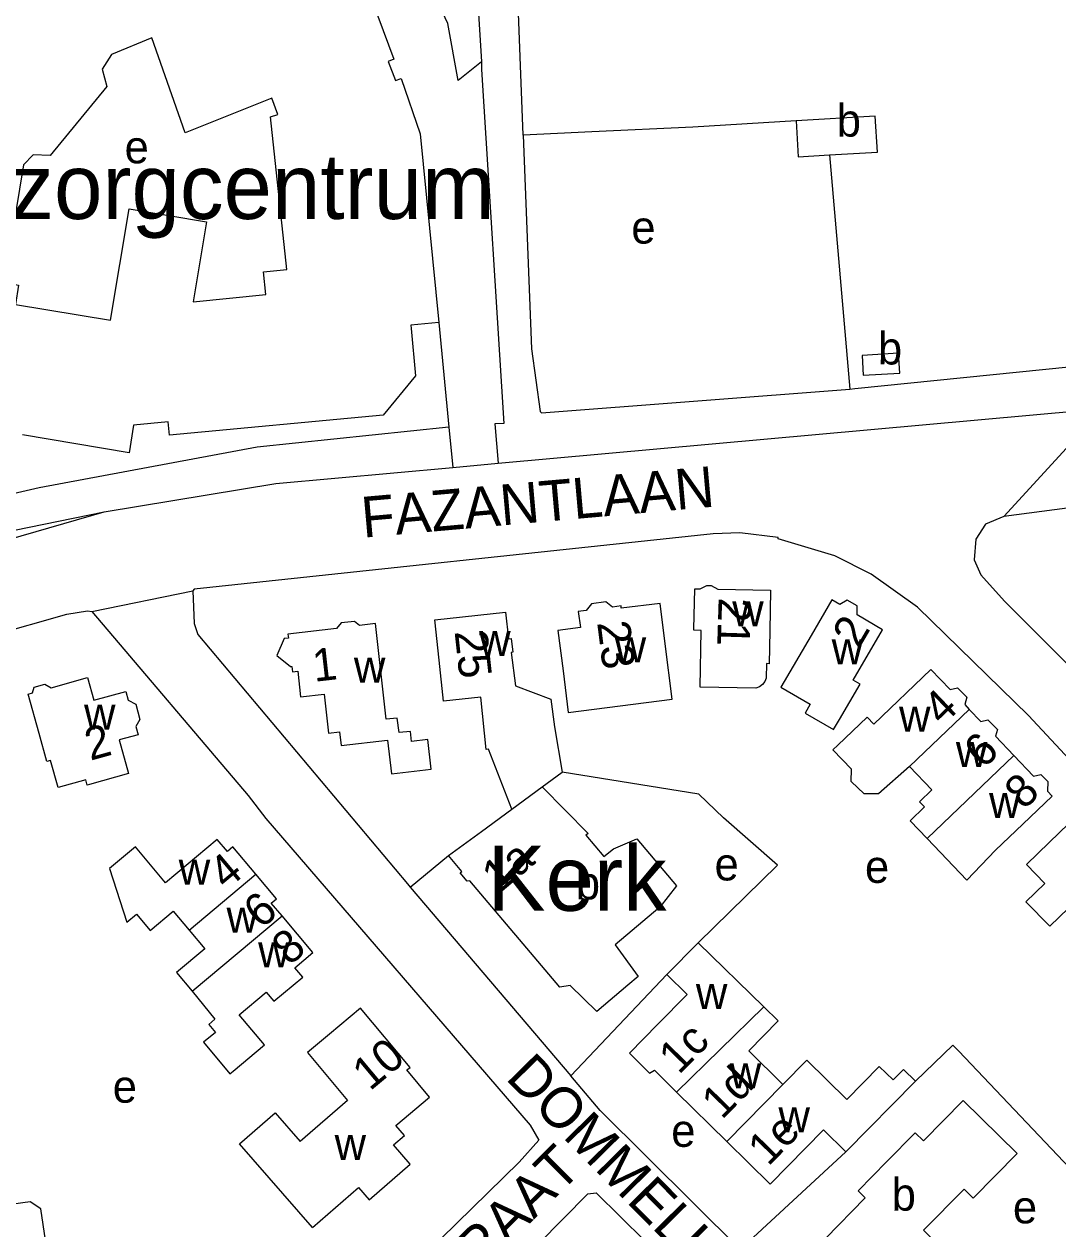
# Model space of a CAD drawing. Extents: x 161775 to 163181, y 382878 to 383925.
# Drawn here: x 162004.9 to 162131.9, y 383389.4 to 383537.4 of the extents above; entities that cross this region are included whole.
import ezdxf

# ---------------------------------------------------------------- set-up
doc = ezdxf.new("R2010")
doc.units = 0
for name, color, linetype in [('BLT_Basislijn', 7, 'Continuous'), ('BLT_Bebouwing', 7, 'Continuous'), ('BLT_Bebouwing_beschrifting', 7, 'Continuous'), ('BLT_Centroide', 7, 'Continuous'), ('BLT_Huisnummer', 7, 'Continuous'), ('BLT_Huisnummer_ tussenligend', 7, 'Continuous'), ('BLT_Onderverdeling_panden', 7, 'Continuous'), ('BLT_Straatnaam', 7, 'Continuous'), ('BLT_Vlakafsluiter', 7, 'Continuous')]:
    doc.layers.add(name, color=color, linetype=linetype)

msp = doc.modelspace()

# ---------------------------------------------------------------- linework, layer by layer
at = {"layer": 'BLT_Basislijn'}
for p, q in [((162074.67, 383524.13), (162066.25, 383523.72)), ((162103.84, 383521.3), (162106.37, 383492.55)), ((162055.89, 383500.73), (162057.11, 383487.85)), ((162063.18, 383483.44), (162137.41, 383490.17)), ((162057.11, 383487.85), (162057.58, 383482.93)), ((162062.77, 383488.27), (162063.18, 383483.44)), ((162052.36, 383431.37), (162057.06, 383435.26)), ((162087.71, 383424.55), (162097.48, 383434.06)), ((162052.36, 383431.37), (162072.1, 383408.19)), ((162092.87, 383386.85), (162105.88, 383398.85))]:
    msp.add_line(p, q, dxfattribs=at)
for points in [[(162066.25, 383523.72), (162064.33, 383574.02)], [(162061.11, 383532.76), (162061.1, 383531.81), (162063.88, 383488.3), (162062.77, 383488.27)], [(162099.75, 383525.49), (162087.08, 383524.73), (162074.67, 383524.13)], [(162066.25, 383523.72), (162067.24, 383497.51), (162068.34, 383489.79), (162068.5, 383489.63), (162106.37, 383492.55)], [(162057.11, 383487.85), (162033.55, 383485.42), (162006.78, 383480.4), (161990.83, 383476.74), (161984.63, 383476.87), (161983.29, 383477.14), (161978.85, 383478.81), (161976.83, 383480.24), (161973.93, 383483.29), (161972.63, 383485.26), (161970.99, 383488.68), (161970, 383493.53), (161968.55, 383506.6), (161967.45, 383522.13)], [(162106.37, 383492.55), (162106.96, 383492.6), (162150.23, 383497)], [(162211.14, 383490.01), (162196.65, 383487.24), (162159.15, 383481.38), (162125.25, 383476.9)], [(162014.8, 383477.46), (162035.87, 383480.96), (162057.58, 383482.93)], [(162057.58, 383482.93), (162063.18, 383483.44)], [(161974.85, 383465.82), (161980.14, 383467.21), (161991.24, 383470.67), (162014.8, 383477.46)], [(161988.9, 383472.18), (162014.8, 383477.46)], [(162125.25, 383476.9), (162123.02, 383475.95), (162121.82, 383474.13), (162121.64, 383471.58), (162122.43, 383469.75), (162125.33, 383466.48), (162163.61, 383428.2), (162170.77, 383419.99), (162181.31, 383409.13), (162201.49, 383387.36), (162220.16, 383368.12), (162237.6, 383349.53), (162241.27, 383346.24)], [(162234.37, 383341.1), (162200.53, 383376.54), (162198.79, 383378.55), (162180.32, 383397.96), (162171.16, 383407.28), (162152.54, 383427.04), (162145.46, 383434.09), (162144.51, 383435.3), (162141.14, 383438.66), (162128.28, 383452.45), (162114.65, 383465.76), (162108.97, 383469.83), (162104.5, 383472.05), (162097.57, 383474.16), (162097.57, 383474.32), (162092.85, 383474.91), (162089.56, 383474.77), (162025.83, 383467.96), (162025.67, 383467.75)], [(162025.67, 383467.75), (162025.82, 383463.74), (162026.27, 383462.41), (162052.03, 383431.77), (162052.36, 383431.37)], [(161973.32, 383454.41), (162010.19, 383464.89), (162012.73, 383465.31), (162013.27, 383465.24)], [(162013.27, 383465.24), (162032.46, 383442.64), (162034.65, 383439.79), (162067.09, 383402.14), (162068.18, 383400.29), (162065.73, 383397.61), (162046.55, 383378.8)], [(162097.48, 383434.06), (162090.82, 383439.89), (162087.79, 383442.81), (162071.02, 383445.48)], [(162072.1, 383408.19), (162083.86, 383420.63)], [(162114.43, 383407.55), (162118.99, 383411.97), (162119.75, 383411.23), (162136.39, 383393.66), (162138.37, 383391.5), (162138.68, 383390.7), (162113.58, 383365.34)], [(162092.87, 383386.85), (162075.69, 383403.95), (162072.1, 383408.19)], [(162036.52, 383357.08), (162059.8, 383379.79), (162066.65, 383386.36), (162068.12, 383387.55), (162074.17, 383393.72), (162075.21, 383393.82), (162093.13, 383376.16), (162097.9, 383371.1)]]:
    msp.add_lwpolyline(points, dxfattribs=at)
at = {"layer": 'BLT_Bebouwing'}
for p, q in [((162059.98, 383551.43), (162061.11, 383532.76)), ((162068.57, 383443.68), (162071.02, 383445.48)), ((162083.86, 383420.63), (162087.71, 383424.55)), ((162095.78, 383416.69), (162087.71, 383424.55)), ((162105.88, 383398.85), (162114.43, 383407.55)), ((162085.08, 383406.2), (162091.26, 383400.12))]:
    msp.add_line(p, q, dxfattribs=at)
for points in [[(162061.11, 383532.76), (162058.27, 383530.46), (162056.98, 383537.43), (162053.91, 383543.98), (162053.43, 383550.99)], [(162044.21, 383549.62), (162050.36, 383533.06), (162049.67, 383532.8), (162050.57, 383530.45), (162051.25, 383530.69), (162053.6, 383523.88), (162055.89, 383500.73)], [(162103.84, 383521.3), (162109.74, 383521.65), (162109.47, 383526.08), (162099.75, 383525.49)], [(162099.75, 383525.49), (162100.01, 383521.07), (162103.84, 383521.3)], [(162055.89, 383500.73), (162052.44, 383500.41), (162052.48, 383500), (162053.02, 383494.18), (162049.04, 383489.36), (162022.81, 383486.88), (162022.65, 383488.52), (162018.37, 383488.12), (162017.85, 383484.72), (162004.75, 383486.93)], [(162107.86, 383496.67), (162108.01, 383494.24), (162112.51, 383494.51), (162112.35, 383496.94), (162107.86, 383496.67)], [(162096.51, 383462.84), (162096.44, 383458.82), (162096.12, 383458.83), (162096.09, 383457.04), (162095.93, 383456.64), (162095.63, 383456.25), (162095.25, 383455.98), (162094.82, 383455.82), (162087.97, 383455.94), (162088.1, 383462.9), (162087.21, 383462.92), (162087.21, 383463.04), (162087.3, 383468.01), (162087.99, 383468), (162088.78, 383468.44), (162089.34, 383468.43), (162090.14, 383467.96), (162096.6, 383467.84), (162096.51, 383462.84)], [(162105.1, 383451.98), (162107.61, 383456.3), (162106.76, 383456.79), (162110.38, 383462.99), (162107.24, 383464.82), (162107.25, 383465.92), (162106.03, 383466.63), (162105.11, 383466.1), (162104.14, 383466.66), (162101.6, 383462.3), (162097.89, 383455.93), (162101.5, 383453.83), (162100.87, 383452.76), (162104.36, 383450.72), (162105.1, 383451.98)], [(162064.84, 383440.94), (162061.97, 383448.33), (162061.71, 383448.3), (162061.02, 383454.72), (162056.46, 383454.23), (162055.91, 383459.27), (162055.37, 383464.21), (162064.08, 383465.16), (162064.43, 383461.89), (162064.77, 383461.93), (162064.96, 383460.22)], [(162083.67, 383461.26), (162083.05, 383466.22), (162078.29, 383465.62), (162078.26, 383465.91), (162077.2, 383465.78), (162076.39, 383466.4), (162074.62, 383466.18), (162073.97, 383465.35), (162073.01, 383465.23), (162073.26, 383463.25), (162070.51, 383462.91), (162071.13, 383457.93), (162071.77, 383452.82), (162084.52, 383454.46), (162083.67, 383461.26)], [(162048.11, 383463.74), (162046.12, 383463.52), (162045.51, 383464.01), (162043.87, 383463.83), (162043.32, 383463.14), (162037.34, 383462.46), (162037.4, 383461.96), (162036.89, 383461.9), (162035.99, 383459.83), (162037.68, 383458.47), (162037.84, 383458.49), (162037.92, 383457.83), (162038.55, 383457.9), (162038.9, 383454.76), (162041.81, 383455.09), (162042.35, 383450.3), (162043.7, 383450.46), (162043.89, 383448.79), (162049.59, 383449.44), (162050.05, 383445.31), (162054.93, 383445.86), (162054.52, 383449.49), (162052.53, 383449.27), (162052.39, 383450.51), (162050.99, 383450.36), (162050.78, 383452.14), (162049.43, 383451.99), (162048.11, 383463.74)], [(162064.96, 383460.22), (162064.75, 383460.2), (162065.3, 383456.1), (162069.65, 383454.45), (162070.1, 383451.06), (162071.02, 383445.48)], [(162113.68, 383446.18), (162109.87, 383442.85), (162108.13, 383442.85), (162106.52, 383444.34), (162106.54, 383445.87), (162104.27, 383448.23), (162104.88, 383448.81), (162108.49, 383452.26), (162109.3, 383451.41), (162116.3, 383458.11), (162118.66, 383455.64), (162119.59, 383455.87), (162120.72, 383454.69), (162120.46, 383453.79), (162121.02, 383453.2)], [(162012.96, 383443.98), (162012.69, 383443.9), (162012.51, 383444.54), (162009.13, 383443.6), (162008.21, 383446.93), (162007.74, 383446.8), (162006.78, 383450.26), (162005.44, 383455.07), (162005.99, 383455.22), (162006.17, 383455.94), (162007.5, 383456.31), (162008.27, 383455.87), (162012.72, 383457.11), (162013.5, 383454.32), (162017.43, 383455.41), (162017.73, 383454.36), (162018.65, 383453.83), (162019.17, 383451.98), (162018.67, 383451.1), (162018.95, 383450.1), (162016.63, 383449.45), (162017.77, 383445.32), (162012.96, 383443.98)], [(162121.02, 383453.2), (162122.43, 383451.73), (162123.31, 383451.94), (162124.47, 383450.73), (162124.23, 383449.9), (162126.49, 383447.54)], [(162126.49, 383447.54), (162128.9, 383445.02), (162129.79, 383445.23), (162130.65, 383444.33), (162130.62, 383443.17), (162131.2, 383442.56), (162127.59, 383439.11), (162124.25, 383435.91), (162120.73, 383432.23), (162115.83, 383437.35)], [(162115.83, 383437.35), (162113.75, 383439.52), (162115.53, 383441.22), (162114.92, 383441.86), (162116.43, 383443.31), (162113.68, 383446.18)], [(162068.57, 383443.68), (162074.21, 383437.97), (162073.94, 383437.74), (162076.15, 383435.12), (162077.32, 383436.1), (162080.2, 383437.29), (162085.05, 383431.55), (162083.04, 383428.92), (162077.55, 383424.27), (162080.35, 383420.4), (162079.09, 383419.33), (162075.27, 383416.1), (162072.01, 383419.31), (162070.76, 383419.08), (162059.68, 383432.17), (162059.37, 383432.11), (162058.51, 383433.14), (162058.71, 383433.31), (162057.06, 383435.26)], [(162057.06, 383435.26), (162061.1, 383438.2), (162064.84, 383440.94)], [(162133.2, 383428.81), (162130.9, 383426.57), (162127.97, 383429.59), (162130.28, 383431.83), (162128.04, 383434.14), (162130.84, 383436.86), (162134.43, 383440.34), (162139.6, 383435.01)], [(162033.4, 383432.98), (162030.6, 383436.32), (162029.91, 383435.74), (162028.66, 383437.23), (162022.32, 383431.92), (162018.61, 383436.34), (162015.42, 383433.66), (162017.57, 383427.06), (162018.76, 383428.06), (162020.44, 383426.05), (162023.26, 383428.42), (162025.2, 383426.11)], [(162036.62, 383427.84), (162035.31, 383429.4), (162035.95, 383429.94), (162033.4, 383432.98)], [(162025.57, 383418.58), (162028.37, 383415.14), (162027.63, 383414.52), (162028.45, 383413.54), (162026.99, 383412.32), (162030.23, 383408.45), (162030.63, 383408.78), (162034.46, 383411.99), (162031.36, 383415.69), (162034.69, 383418.47), (162035.63, 383417.35), (162039.16, 383420.32), (162038.19, 383421.48), (162040.4, 383423.33), (162036.62, 383427.84)], [(162025.2, 383426.11), (162027.13, 383423.8), (162023.65, 383420.88), (162025.57, 383418.58)], [(162083.86, 383420.63), (162086.36, 383418.18)], [(162086.36, 383418.18), (162082.78, 383414.54), (162079.28, 383410.97), (162081.77, 383408.52), (162082.35, 383408.88), (162085.08, 383406.2)], [(162040.36, 383389.56), (162046, 383394.47), (162047.32, 383392.95), (162052.38, 383397.34), (162050.32, 383399.71), (162051.67, 383400.89), (162050.6, 383402.12), (162054.74, 383405.59), (162051.96, 383408.92), (162052.35, 383409.24), (162046.28, 383416.51), (162042.44, 383413.3)], [(162095.78, 383416.69), (162097.56, 383414.95), (162093.93, 383411.25), (162098.14, 383407.12)], [(162042.44, 383413.3), (162039.76, 383411.06), (162044.67, 383405.18), (162038.86, 383400.14)], [(162114.43, 383407.55), (162112.94, 383408.98), (162111.67, 383407.69), (162109.97, 383409.36), (162105.97, 383405.3), (162101.07, 383410.11), (162098.14, 383407.12)], [(162121.43, 383377.49), (162117.92, 383373.92), (162103.35, 383388.24), (162108.24, 383393.22), (162107.37, 383394.08), (162110.9, 383397.66), (162114.39, 383401.21), (162115.42, 383400.2), (162120.29, 383405.15), (162126.89, 383398.67), (162121.51, 383393.18), (162120.38, 383394.3), (162115.4, 383389.24), (162124.34, 383380.46), (162121.43, 383377.49)], [(162040.36, 383389.56), (162031.42, 383399.85), (162035.79, 383403.66), (162038.86, 383400.14)], [(162091.26, 383400.12), (162096.59, 383394.89), (162103.13, 383401.55), (162105.88, 383398.85)], [(162007.87, 383386.1), (162006.99, 383391.88), (162005.69, 383392.74), (162003.6, 383392.42), (162003.39, 383393.81), (162000, 383393.3), (161996.63, 383392.79), (161996.8, 383391.67), (161993.25, 383391.13), (161993.6, 383388.79), (161992.03, 383388.55), (161992.75, 383383.82)]]:
    msp.add_lwpolyline(points, dxfattribs=at)
msp.add_lwpolyline([(162020.62, 383535.67), (162015.69, 383533.63), (162014.54, 383531.84), (162015.11, 383529.72), (162008.15, 383521.23), (162006.07, 383521.3), (162004.87, 383520.08), (162002.52, 383505.62), (162004.27, 383505.33), (162003.88, 383502.92), (162015.57, 383501.02), (162017.86, 383514.68), (162027.34, 383513.1), (162025.7, 383503.26), (162034.64, 383504.16), (162034.36, 383506.93), (162037.22, 383507.22), (162035.19, 383526), (162036.09, 383526.29), (162035.39, 383528.29), (162024.73, 383524.03)], close=True, dxfattribs=at)
at = {"layer": 'BLT_Onderverdeling_panden'}
for p, q in [((162121.02, 383453.2), (162113.68, 383446.18)), ((162115.83, 383437.35), (162126.49, 383447.54)), ((162064.84, 383440.94), (162068.57, 383443.68)), ((162025.2, 383426.11), (162033.4, 383432.98)), ((162025.57, 383418.58), (162036.62, 383427.84)), ((162095.78, 383416.69), (162085.08, 383406.2)), ((162098.14, 383407.12), (162091.26, 383400.12))]:
    msp.add_line(p, q, dxfattribs=at)
at = {"layer": 'BLT_Vlakafsluiter'}
for p, q in [((162137.41, 383490.17), (162125.25, 383476.9)), ((162013.27, 383465.24), (162025.67, 383467.75))]:
    msp.add_line(p, q, dxfattribs=at)

# ---------------------------------------------------------------- texts
at = {"layer": 'BLT_Bebouwing_beschrifting'}
for s, p in [('Woonzorgcentrum', (161975.33, 383513.44)), ('Kerk', (162061.85, 383428.47))]:
    msp.add_text(s, height=8, dxfattribs=at).set_placement(p)
at = {"layer": 'BLT_Centroide'}
for s, p in [('b', (162104.74, 383523.56)), ('e', (162017.29, 383520.28)), ('e', (162079.52, 383510.42)), ('b', (162109.8, 383495.57)), ('w', (162091.91, 383463.42)), ('w', (162060.83, 383459.75)), ('w', (162077.48, 383459)), ('w', (162104.12, 383458.75)), ('w', (162045.45, 383456.48)), ('w', (162012.31, 383450.73)), ('w', (162112.4, 383450.47)), ('w', (162119.38, 383446.12)), ('w', (162123.45, 383439.88)), ('w', (162023.94, 383431.66)), ('b', (162072.7, 383429.88)), ('e', (162089.74, 383432.2)), ('e', (162108.21, 383431.9)), ('w', (162029.81, 383425.78)), ('w', (162033.69, 383421.52)), ('w', (162087.45, 383416.39)), ('w', (162091.61, 383406.66)), ('e', (162015.83, 383404.9)), ('w', (162097.59, 383401.25)), ('e', (162084.42, 383399.48)), ('w', (162043.08, 383397.88)), ('b', (162111.49, 383391.65)), ('e', (162126.38, 383390.08))]:
    msp.add_text(s, height=4, dxfattribs=at).set_placement(p)
at = {"layer": 'BLT_Huisnummer'}
for s, rotation, p in [('21', 268.2283, (162090.25, 383466.96)), ('23', 277.1463, (162075.32, 383463.87)), ('2', 59.762, (162107.46, 383460.56)), ('25', 276.2027, (162057.81, 383462.77)), ('1', 6.4397, (162040.59, 383456.59)), ('4', 43.7194, (162117.71, 383451.09)), ('2', 15.5345, (162013.07, 383446.89)), ('8', 43.7232, (162127.72, 383440.78)), ('4', 39.9612, (162029.78, 383430.93)), ('1a', 40.2384, (162063.33, 383430.55)), ('8', 39.9694, (162037.52, 383421.64)), ('1c', 45.5017, (162085.37, 383408.26)), ('10', 39.8783, (162047.41, 383406.26)), ('1e', 45.5105, (162096.32, 383396.99))]:
    msp.add_text(s, height=4, rotation=rotation, dxfattribs=at).set_placement(p)
at = {"layer": 'BLT_Huisnummer_ tussenligend'}
for s, rotation, p in [('6', 43.7194, (162122.74, 383445.8)), ('6', 39.9612, (162034.05, 383426.15)), ('1d', 45.4998, (162090.63, 383402.72))]:
    msp.add_text(s, height=4, rotation=rotation, dxfattribs=at).set_placement(p)
at = {"layer": 'BLT_Straatnaam'}
for s, rotation, p in [('FAZANTLAAN', 5.054, (162046.58, 383474.29)), ('DOMMELHOEFSTRAAT', 314.5461, (162063.96, 383407.85)), ('PATRIJSSTRAAT', 44.7741, (162035.36, 383358.61))]:
    msp.add_text(s, height=5, rotation=rotation, dxfattribs=at).set_placement(p)

doc.saveas('drawing.dxf')
